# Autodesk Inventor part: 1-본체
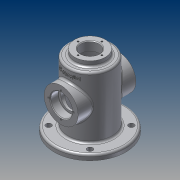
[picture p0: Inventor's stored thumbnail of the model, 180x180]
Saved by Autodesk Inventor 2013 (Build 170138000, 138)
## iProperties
Created: 2014-12
Part Number: 1-본체
Material: 알루미늄 6061
Document SubType Name: Modeling
Designer: CAD-B16
Mass: 479.544 g
Surface Area: 607.62 cm^2
Volume: 176.954 cm^3
Density: 2.71 g/cm^3
Author: CAD-B16
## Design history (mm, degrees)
sketch "스케치1"
  geometry: L1 (0, 45)-(0, -45); L2 (0, 45)-(32.5, 45); L3 (32.5, 45)-(32.5, -45); L4 (32.5, -45)-(0, -45); 2 further points
  constraints: 8 end point, 3 perpendicular, 1 coincident, 1 midpoint, 1 vertical
  dimensions: "d0" = 90 distance of L1.start L1.end; "d2" = 65 diameter of L3 L1
revolve "회전1" sketch "스케치1" stored, may be unused: angle "d3" = 90 deg
feature "쉘1" dims "d4" = 5
sketch "스케치2"
  geometry: C1 r 52.5 at (0, 0); C2 r 27.5 at (0, 0) reference; 1 further point
  constraints: 1 centre point, 1 coincident
  dimensions: "d5" = 105 diameter of C1
extrude "돌출1" join sketch "스케치2" distance "d7" = 8; taper "d8" = 0 deg
node "작업 평면1"
sketch "스케치3"
  geometry: C1 r 22.5 at (0, 0); 1 further point
  constraints: 1 centre point, 1 coincident
  dimensions: "d10" = 45 diameter of C1
extrude "돌출2" join sketch "스케치3" stored distance "d11" = 8; taper "d12" = 0 deg
hole "구멍1" diameter "d15" = 27; stored, may be unused: countersink angle "d19" = 90 deg, drill point angle "d21" = 0 deg; dims "d13" = 10, "d14" = 10, "d16" = 6, "d17" = 4, "d18" = 2, "d20" = 8
sketch "스케치4"
  geometry: 2 further points
  dimensions: "d22" = 17.5 distance of point (0, 0) point (0, 17.5)
hole "구멍2" sketch "스케치4" at (0, 17.5) diameter "d23" = 2.459; stored, may be unused: countersink angle "d27" = 90 deg, drill point angle "d29" = 118 deg; dims "d24" = 6, "d25" = 4, "d26" = 2, "d28" = 8
sketch "스케치5"
  geometry: L1 (0, 0)-(30.406, 30.406); L2 (0, 0)-(43, 0); C1 r 4 at (30.406, 30.406)
  constraints: 4 end point, 1 centre point, 1 coincident, 1 equal length, 1 horizontal
  dimensions: "d33" = 43 distance of L1.start L1.end; "d34" = 45 deg angle of L2 L1; "d35" = 8 diameter of C1
extrude "돌출3" cut sketch "스케치5" stored distance "d36" = 8; taper "d37" = 0 deg
node "작업 평면2"
sketch "스케치6"
  geometry: L1 (-53, 52.5)-(-53, -52.5) reference; C1 r 25 at (2, 0)
  constraints: 1 centre point
  dimensions: "d78" = 55 distance from line of L1 C1.centre
extrude "돌출4" join sketch "스케치6" stored distance "d43" = 8; taper "d44" = 0 deg
sketch "스케치7"
  geometry: 2 further points
  dimensions: "d45" = 20.5 distance of point (0, -2) point (0, 18.5)
hole "구멍3" sketch "스케치7" at (0, 18.5) diameter "d46" = 2.459; stored, may be unused: countersink angle "d50" = 90 deg, drill point angle "d52" = 118 deg; dims "d47" = 6, "d48" = 4, "d49" = 2, "d51" = 8
hole "구멍4" diameter "d58" = 25; stored, may be unused: countersink angle "d62" = 90 deg, drill point angle "d64" = 0 deg; dims "d56" = 10, "d57" = 10, "d59" = 6, "d60" = 32, "d61" = 12, "d63" = 8
node "작업 평면3"
chamfer "모따기1" distance "d69" = 1; stored, may be unused: second distance "d70" = 2, angle "d71" = 45 deg
fillet "모깎기1" dims "d72" = 3
fillet "모깎기2" dims "d73" = 0.3
node "작업 평면4"
sketch "스케치9"
  geometry: L1 (45, 29.5)-(45, -29.5) reference; 2 further points
  constraints: 1 horizontal alignment, 1 other
  dimensions: "d75" = 9 distance from line of L1 point (36, 0)
feature "엠보싱2" sketch "스케치9" dims "d0" = 90, "d2" = 65, "d11" = 8, "d12" = 0, "d76" = 1, "d77" = 0
node "솔리드1"
pattern_circular "원형 패턴1" dims angle "d31" = 360 deg
pattern_circular "원형 패턴2" dims angle "d39" = 360 deg
pattern_circular "원형 패턴3" dims angle "d54" = 360 deg
mirror "대칭1"
other parameters: "d9" = -106, "d41" = 42.5, "d65" = 32.5, "d74" = 32.5
